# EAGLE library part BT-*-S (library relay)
KLEIN RELAIS WASCHDICHT 2 Wechsler Distriibutor: Conrad Electronic, Bestell Nr.: 505226-13 - 24V 505226-13 - 5V 505170-13 - 12V 505170-13 - 48V Bestar Electric Ltd. Source: http://www2.produktinfo.conrad.com/datenblaetter/500000-524999/505226-da-01-en-Kleinrelais_waschdicht_24V.pdf
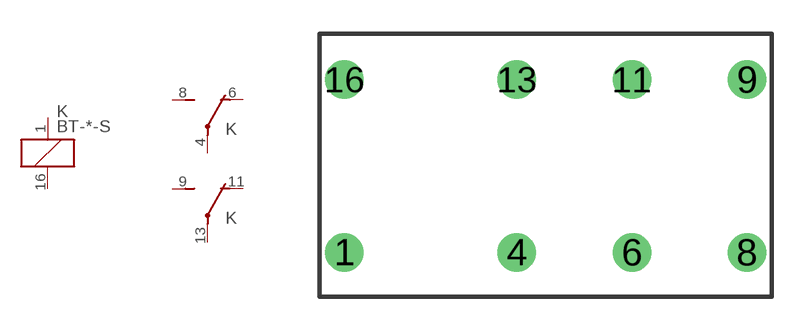
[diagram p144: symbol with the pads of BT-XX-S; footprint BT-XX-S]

Designator prefix K; gates K=K -1=U -2=U

## BT-5-S (OC_FARNELL: unknown; OC_NEWARK: unknown), BT-6-S (OC_FARNELL: unknown; OC_NEWARK: unknown), BT-9-S (OC_FARNELL: unknown; OC_NEWARK: unknown), BT-12-S (OC_FARNELL: unknown; OC_NEWARK: unknown), BT-24-S (OC_FARNELL: unknown; OC_NEWARK: unknown), BT-48-S (OC_FARNELL: unknown; OC_NEWARK: unknown)  [BT-XX-S]
1  K:1  pas
4  -1:P  pas
6  -1:O  pas
8  -1:S  pas
9  -2:S  pas
11  -2:O  pas
13  -2:P  pas
16  K:2  pas

## Footprint BT-XX-S (pad centres in mm)
Bestar Electric Ltd. Source: http://www2.produktinfo.conrad.com/datenblaetter/500000-524999/505226-da-01-en-Kleinrelais_waschdicht_24V.pdf
drill 1 pad 1.7 round: 1 -8.89,-3.81; 4 -1.27,-3.81; 6 3.81,-3.81; 8 8.89,-3.81; 9 8.89,3.81; 11 3.81,3.81; 13 -1.27,3.81; 16 -8.89,3.81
